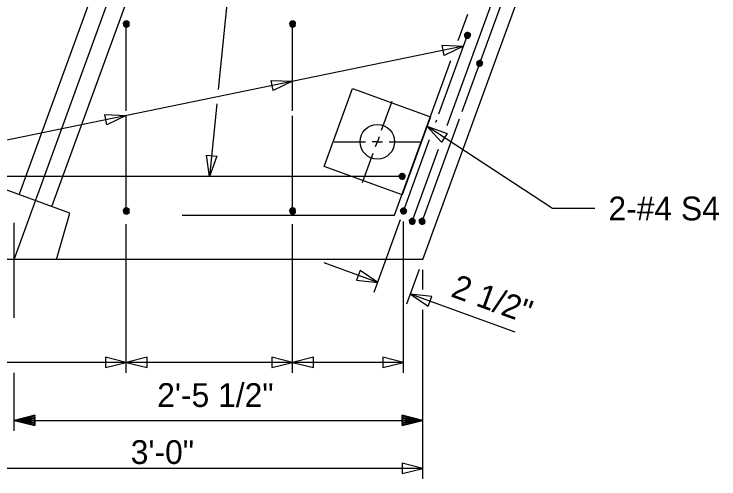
# Model space of a CAD drawing. Extents: x -408 to -23, y -15 to 117.
# Drawn here: x -86.987 to -82.749, y 40.166 to 42.962 of the extents above; entities that cross this region are included whole.
import ezdxf

# ---------------------------------------------------------------- set-up
doc = ezdxf.new("R2010")
doc.units = 0
for name, color, linetype in [('Arrowhead Terminators CELL', 7, 'Continuous'), ('Dimension Lines', 7, 'Continuous'), ('Mis Center Lines', 7, 'Continuous'), ('Rebar Lines', 7, 'Continuous'), ('Sup Concrete Girder Lines', 7, 'Continuous'), ('Sup Cored Slab Unit', 7, 'Continuous'), ('Text', 7, 'Continuous')]:
    doc.layers.add(name, color=color, linetype=linetype)

msp = doc.modelspace()

# ---------------------------------------------------------------- linework, layer by layer
at = {"layer": 'Arrowhead Terminators CELL'}
for points in [[(-84.2846, 42.7692), (-84.4008, 42.7134), (-84.4134, 42.7746)], [(-85.3123, 42.5577), (-85.4284, 42.5019), (-85.441, 42.5632)], [(-86.3123, 42.352), (-86.4284, 42.2962), (-86.441, 42.3574)], [(-84.5044, 42.287), (-84.3827, 42.2446), (-84.417, 42.1924)], [(-85.8118, 41.9859), (-85.8305, 42.1134), (-85.7683, 42.1072)], [(-84.8, 41.3484), (-84.9068, 41.4206), (-84.9282, 41.3619)], [(-84.6043, 41.2772), (-84.4975, 41.2051), (-84.4761, 41.2638)], [(-86.3123, 40.8667), (-86.4373, 40.898), (-86.4373, 40.8355)], [(-86.3123, 40.8667), (-86.1873, 40.8355), (-86.1873, 40.898)], [(-85.3123, 40.8667), (-85.4373, 40.898), (-85.4373, 40.8355)], [(-85.3123, 40.8667), (-85.1873, 40.8355), (-85.1873, 40.898)], [(-84.6456, 40.8667), (-84.7706, 40.898), (-84.7706, 40.8355)], [(-84.5284, 40.229), (-84.6534, 40.2603), (-84.6534, 40.1978)]]:
    msp.add_lwpolyline(points, close=True, dxfattribs=at)
at = {"layer": 'Dimension Lines'}
for p, q in [((-85.6503, 43.6051), (-85.7597, 42.5082)), ((-85.7684, 42.4213), (-85.8118, 41.9859)), ((-84.7776, 42.2631), (-84.7134, 42.4392)), ((-85.0617, 42.1944), (-84.8741, 42.1944)), ((-84.731, 42.1945), (-84.5435, 42.1944)), ((-84.8917, 41.9496), (-84.8275, 42.1258)), ((-86.9867, 41.134), (-86.9867, 41.7067)), ((-84.8214, 41.2897), (-84.6627, 41.7261)), ((-84.6456, 40.8037), (-84.6456, 41.715)), ((-86.3123, 40.8037), (-86.3123, 41.6974)), ((-85.3123, 40.8037), (-85.3123, 41.6974)), ((-84.8, 41.3484), (-85.1233, 41.4662)), ((-84.6257, 41.2184), (-84.5498, 41.4271)), ((-84.5284, 41.3057), (-84.5284, 41.4234)), ((-83.9743, 41.0479), (-84.6043, 41.2772)), ((-84.5284, 40.166), (-84.5284, 41.1822)), ((-86.3123, 40.8667), (-87.3123, 40.8667)), ((-85.3123, 40.8667), (-86.3123, 40.8667)), ((-84.6456, 40.8667), (-85.3123, 40.8667)), ((-86.9867, 40.4548), (-86.9867, 40.8042)), ((-86.9867, 40.5178), (-84.5284, 40.5178)), ((-84.5284, 40.229), (-87.5284, 40.229))]:
    msp.add_line(p, q, dxfattribs=at)
for points in [[(-84.2846, 42.7692), (-88.3544, 41.9318), (-88.4563, 41.9318)], [(-83.4943, 41.7927), (-83.7502, 41.7927), (-84.5044, 42.287)], [(-84.7917, 42.2239), (-84.8026, 42.1944), (-84.771, 42.1943)], [(-84.8135, 42.1648), (-84.8029, 42.1942), (-84.8343, 42.1943)], [(-86.8617, 40.5178), (-86.8617, 40.5115), (-86.9867, 40.5178), (-86.8617, 40.5053), (-86.8617, 40.499), (-86.9867, 40.5178), (-86.8617, 40.4928), (-86.8617, 40.4865), (-86.9867, 40.5178), (-86.8617, 40.549), (-86.8617, 40.5428), (-86.9867, 40.5178), (-86.8617, 40.5365), (-86.8617, 40.5303), (-86.9867, 40.5178), (-86.8617, 40.524), (-86.8617, 40.4865), (-86.8617, 40.549), (-86.9867, 40.5178), (-86.8617, 40.4865)], [(-84.6534, 40.5178), (-84.6534, 40.524), (-84.5284, 40.5178), (-84.6534, 40.5303), (-84.6534, 40.5365), (-84.5284, 40.5178), (-84.6534, 40.5428), (-84.6534, 40.549), (-84.5284, 40.5178), (-84.6534, 40.4865), (-84.6534, 40.4928), (-84.5284, 40.5178), (-84.6534, 40.499), (-84.6534, 40.5053), (-84.5284, 40.5178), (-84.6534, 40.5115), (-84.6534, 40.549), (-84.6534, 40.4865), (-84.5284, 40.5178), (-84.6534, 40.549)]]:
    msp.add_lwpolyline(points, dxfattribs=at)
at = {"layer": 'Mis Center Lines'}
msp.add_line((-86.9867, 41.4859), (-85.9162, 44.4271), dxfattribs=at)
at = {"layer": 'Rebar Lines'}
for p, q in [((-84.2927, 42.3769), (-83.9898, 43.209)), ((-84.3834, 42.292), (-84.0677, 43.1594)), ((-84.3164, 42.8036), (-84.2587, 42.962)), ((-86.3123, 42.3911), (-86.3123, 42.9025)), ((-86.3123, 42.3793), (-86.3123, 42.9025)), ((-85.3123, 42.3911), (-85.3123, 42.9025)), ((-85.3123, 42.3793), (-85.3123, 42.9025)), ((-84.4328, 42.3621), (-84.2608, 42.8347)), ((-84.6993, 41.7515), (-84.3602, 42.6831)), ((-86.3123, 41.7775), (-86.3123, 42.3502)), ((-85.3123, 41.7775), (-85.3123, 42.3502)), ((-84.5336, 41.715), (-84.3094, 42.3312)), ((-84.4509, 42.3125), (-84.4458, 42.3264)), ((-84.6456, 41.7775), (-84.4887, 42.2086)), ((-84.5934, 41.715), (-84.4349, 42.1504)), ((-84.6536, 41.9859), (-87.3411, 41.9859)), ((-85.9761, 41.7515), (-84.6993, 41.7515))]:
    msp.add_line(p, q, dxfattribs=at)
for points in [[(-86.2947, 42.9025), (-86.296, 42.9092), (-86.2998, 42.915), (-86.3055, 42.9188), (-86.3123, 42.9201), (-86.319, 42.9188), (-86.3247, 42.915), (-86.3285, 42.9093), (-86.3299, 42.9025), (-86.3285, 42.8958), (-86.3247, 42.8901), (-86.319, 42.8862), (-86.3123, 42.8849), (-86.3055, 42.8862), (-86.2998, 42.89), (-86.296, 42.8957), (-86.2947, 42.9025), (-86.3123, 42.9025), (-86.3299, 42.9025), (-86.3285, 42.9093), (-86.3123, 42.9025), (-86.3247, 42.915), (-86.319, 42.9188), (-86.3123, 42.9025), (-86.3123, 42.9201), (-86.3055, 42.9188), (-86.3123, 42.9025), (-86.2998, 42.915), (-86.296, 42.9092), (-86.3123, 42.9025), (-86.296, 42.8957), (-86.2998, 42.89), (-86.3123, 42.9025), (-86.3055, 42.8862), (-86.3123, 42.8849), (-86.3123, 42.9025), (-86.319, 42.8862), (-86.3247, 42.8901), (-86.3123, 42.9025), (-86.3285, 42.8958)], [(-85.2947, 42.9025), (-85.296, 42.9092), (-85.2998, 42.915), (-85.3055, 42.9188), (-85.3123, 42.9201), (-85.319, 42.9188), (-85.3247, 42.915), (-85.3285, 42.9093), (-85.3299, 42.9025), (-85.3285, 42.8958), (-85.3247, 42.8901), (-85.319, 42.8862), (-85.3123, 42.8849), (-85.3055, 42.8862), (-85.2998, 42.89), (-85.296, 42.8957), (-85.2947, 42.9025), (-85.3123, 42.9025), (-85.3299, 42.9025), (-85.3285, 42.9093), (-85.3123, 42.9025), (-85.3247, 42.915), (-85.319, 42.9188), (-85.3123, 42.9025), (-85.3123, 42.9201), (-85.3055, 42.9188), (-85.3123, 42.9025), (-85.2998, 42.915), (-85.296, 42.9092), (-85.3123, 42.9025), (-85.296, 42.8957), (-85.2998, 42.89), (-85.3123, 42.9025), (-85.3055, 42.8862), (-85.3123, 42.8849), (-85.3123, 42.9025), (-85.319, 42.8862), (-85.3247, 42.8901), (-85.3123, 42.9025), (-85.3285, 42.8958)], [(-84.2435, 42.8317), (-84.2436, 42.8385), (-84.2463, 42.8448), (-84.2513, 42.8496), (-84.2577, 42.852), (-84.2646, 42.8519), (-84.2709, 42.8491), (-84.2757, 42.8442), (-84.2782, 42.8378), (-84.278, 42.8309), (-84.2752, 42.8246), (-84.2703, 42.8199), (-84.2639, 42.8174), (-84.257, 42.8175), (-84.2507, 42.8203), (-84.2459, 42.8252), (-84.2435, 42.8317), (-84.2608, 42.8347), (-84.2782, 42.8378), (-84.2757, 42.8442), (-84.2608, 42.8347), (-84.2709, 42.8491), (-84.2646, 42.8519), (-84.2608, 42.8347), (-84.2577, 42.852), (-84.2513, 42.8496), (-84.2608, 42.8347), (-84.2463, 42.8448), (-84.2436, 42.8385), (-84.2608, 42.8347), (-84.2459, 42.8252), (-84.2507, 42.8203), (-84.2608, 42.8347), (-84.257, 42.8175), (-84.2639, 42.8174), (-84.2608, 42.8347), (-84.2703, 42.8199), (-84.2752, 42.8246), (-84.2608, 42.8347), (-84.278, 42.8309)], [(-84.1704, 42.6623), (-84.1705, 42.6691), (-84.1733, 42.6754), (-84.1783, 42.6802), (-84.1847, 42.6827), (-84.1915, 42.6826), (-84.1978, 42.6798), (-84.2026, 42.6748), (-84.2051, 42.6684), (-84.2049, 42.6615), (-84.2022, 42.6552), (-84.1972, 42.6504), (-84.1908, 42.6479), (-84.1839, 42.6481), (-84.1776, 42.6508), (-84.1728, 42.6558), (-84.1704, 42.6623), (-84.1877, 42.6653), (-84.2051, 42.6684), (-84.2026, 42.6748), (-84.1877, 42.6653), (-84.1978, 42.6798), (-84.1915, 42.6826), (-84.1877, 42.6653), (-84.1847, 42.6827), (-84.1783, 42.6802), (-84.1877, 42.6653), (-84.1733, 42.6754), (-84.1705, 42.6691), (-84.1877, 42.6653), (-84.1728, 42.6558), (-84.1776, 42.6508), (-84.1877, 42.6653), (-84.1839, 42.6481), (-84.1908, 42.6479), (-84.1877, 42.6653), (-84.1972, 42.6504), (-84.2022, 42.6552), (-84.1877, 42.6653), (-84.2049, 42.6615)], [(-84.6363, 41.9828), (-84.6364, 41.9897), (-84.6391, 41.996), (-84.6441, 42.0008), (-84.6506, 42.0032), (-84.6574, 42.0031), (-84.6637, 42.0003), (-84.6684, 41.9954), (-84.6709, 41.989), (-84.6708, 41.9821), (-84.668, 41.9758), (-84.6631, 41.971), (-84.6566, 41.9685), (-84.6498, 41.9687), (-84.6435, 41.9714), (-84.6387, 41.9764), (-84.6363, 41.9828), (-84.6536, 41.9859), (-84.6709, 41.989), (-84.6684, 41.9954), (-84.6536, 41.9859), (-84.6637, 42.0003), (-84.6574, 42.0031), (-84.6536, 41.9859), (-84.6506, 42.0032), (-84.6441, 42.0008), (-84.6536, 41.9859), (-84.6391, 41.996), (-84.6364, 41.9897), (-84.6536, 41.9859), (-84.6387, 41.9764), (-84.6435, 41.9714), (-84.6536, 41.9859), (-84.6498, 41.9687), (-84.6566, 41.9685), (-84.6536, 41.9859), (-84.6631, 41.971), (-84.668, 41.9758), (-84.6536, 41.9859), (-84.6708, 41.9821)], [(-86.2947, 41.7775), (-86.296, 41.7842), (-86.2998, 41.79), (-86.3055, 41.7938), (-86.3123, 41.7951), (-86.319, 41.7938), (-86.3247, 41.79), (-86.3285, 41.7843), (-86.3299, 41.7775), (-86.3285, 41.7708), (-86.3247, 41.7651), (-86.319, 41.7612), (-86.3123, 41.7599), (-86.3055, 41.7612), (-86.2998, 41.765), (-86.296, 41.7707), (-86.2947, 41.7775), (-86.3123, 41.7775), (-86.3299, 41.7775), (-86.3285, 41.7843), (-86.3123, 41.7775), (-86.3247, 41.79), (-86.319, 41.7938), (-86.3123, 41.7775), (-86.3123, 41.7951), (-86.3055, 41.7938), (-86.3123, 41.7775), (-86.2998, 41.79), (-86.296, 41.7842), (-86.3123, 41.7775), (-86.296, 41.7707), (-86.2998, 41.765), (-86.3123, 41.7775), (-86.3055, 41.7612), (-86.3123, 41.7599), (-86.3123, 41.7775), (-86.319, 41.7612), (-86.3247, 41.7651), (-86.3123, 41.7775), (-86.3285, 41.7708)], [(-85.2947, 41.7775), (-85.296, 41.7842), (-85.2998, 41.79), (-85.3055, 41.7938), (-85.3123, 41.7951), (-85.319, 41.7938), (-85.3247, 41.79), (-85.3285, 41.7843), (-85.3299, 41.7775), (-85.3285, 41.7708), (-85.3247, 41.7651), (-85.319, 41.7612), (-85.3123, 41.7599), (-85.3055, 41.7612), (-85.2998, 41.765), (-85.296, 41.7707), (-85.2947, 41.7775), (-85.3123, 41.7775), (-85.3299, 41.7775), (-85.3285, 41.7843), (-85.3123, 41.7775), (-85.3247, 41.79), (-85.319, 41.7938), (-85.3123, 41.7775), (-85.3123, 41.7951), (-85.3055, 41.7938), (-85.3123, 41.7775), (-85.2998, 41.79), (-85.296, 41.7842), (-85.3123, 41.7775), (-85.296, 41.7707), (-85.2998, 41.765), (-85.3123, 41.7775), (-85.3055, 41.7612), (-85.3123, 41.7599), (-85.3123, 41.7775), (-85.319, 41.7612), (-85.3247, 41.7651), (-85.3123, 41.7775), (-85.3285, 41.7708)], [(-84.6283, 41.7744), (-84.6284, 41.7813), (-84.6311, 41.7876), (-84.6361, 41.7924), (-84.6425, 41.7949), (-84.6493, 41.7948), (-84.6557, 41.7919), (-84.6604, 41.787), (-84.6629, 41.7806), (-84.6627, 41.7737), (-84.66, 41.7674), (-84.6551, 41.7626), (-84.6487, 41.7601), (-84.6417, 41.7603), (-84.6355, 41.763), (-84.6307, 41.768), (-84.6283, 41.7744), (-84.6456, 41.7775), (-84.6629, 41.7806), (-84.6604, 41.787), (-84.6456, 41.7775), (-84.6557, 41.7919), (-84.6493, 41.7948), (-84.6456, 41.7775), (-84.6425, 41.7949), (-84.6361, 41.7924), (-84.6456, 41.7775), (-84.6311, 41.7876), (-84.6284, 41.7813), (-84.6456, 41.7775), (-84.6307, 41.768), (-84.6355, 41.763), (-84.6456, 41.7775), (-84.6417, 41.7603), (-84.6487, 41.7601), (-84.6456, 41.7775), (-84.6551, 41.7626), (-84.66, 41.7674), (-84.6456, 41.7775), (-84.6627, 41.7737)], [(-84.576, 41.712), (-84.5762, 41.7188), (-84.5789, 41.7251), (-84.5839, 41.7299), (-84.5903, 41.7324), (-84.5972, 41.7323), (-84.6035, 41.7294), (-84.6082, 41.7245), (-84.6107, 41.7181), (-84.6105, 41.7113), (-84.6078, 41.705), (-84.6029, 41.7002), (-84.5964, 41.6977), (-84.5896, 41.6978), (-84.5833, 41.7006), (-84.5785, 41.7055), (-84.576, 41.712), (-84.5934, 41.715), (-84.6107, 41.7181), (-84.6082, 41.7245), (-84.5934, 41.715), (-84.6035, 41.7294), (-84.5972, 41.7323), (-84.5934, 41.715), (-84.5903, 41.7324), (-84.5839, 41.7299), (-84.5934, 41.715), (-84.5789, 41.7251), (-84.5762, 41.7188), (-84.5934, 41.715), (-84.5785, 41.7055), (-84.5833, 41.7006), (-84.5934, 41.715), (-84.5896, 41.6978), (-84.5964, 41.6977), (-84.5934, 41.715), (-84.6029, 41.7002), (-84.6078, 41.705), (-84.5934, 41.715), (-84.6105, 41.7113)], [(-84.5163, 41.7119), (-84.5164, 41.7188), (-84.5191, 41.7251), (-84.5241, 41.7299), (-84.5305, 41.7324), (-84.5374, 41.7323), (-84.5437, 41.7294), (-84.5484, 41.7245), (-84.5509, 41.7181), (-84.5508, 41.7112), (-84.548, 41.7049), (-84.5431, 41.7001), (-84.5366, 41.6976), (-84.5298, 41.6978), (-84.5235, 41.7005), (-84.5187, 41.7055), (-84.5163, 41.7119), (-84.5336, 41.715), (-84.5509, 41.7181), (-84.5484, 41.7245), (-84.5336, 41.715), (-84.5437, 41.7294), (-84.5374, 41.7323), (-84.5336, 41.715), (-84.5305, 41.7324), (-84.5241, 41.7299), (-84.5336, 41.715), (-84.5191, 41.7251), (-84.5164, 41.7188), (-84.5336, 41.715), (-84.5187, 41.7055), (-84.5235, 41.7005), (-84.5336, 41.715), (-84.5298, 41.6978), (-84.5366, 41.6976), (-84.5336, 41.715), (-84.5431, 41.7001), (-84.548, 41.7049), (-84.5336, 41.715), (-84.5508, 41.7112)]]:
    msp.add_lwpolyline(points, dxfattribs=at)
at = {"layer": 'Sup Concrete Girder Lines'}
for p, q in [((-86.9557, 41.8757), (-86.0056, 44.4859)), ((-86.7599, 41.8044), (-85.7839, 44.4859)), ((-84.5284, 41.4859), (-83.4578, 44.4271)), ((-84.5284, 41.4859), (-88.2718, 41.4859))]:
    msp.add_line(p, q, dxfattribs=at)
msp.add_lwpolyline([(-86.7318, 41.4859), (-86.6523, 41.7652), (-87.0634, 41.9149), (-87.2417, 41.4859)], dxfattribs=at)
msp.add_circle((-84.8029, 42.1942), 0.1042, dxfattribs=at)
at = {"layer": 'Sup Cored Slab Unit'}
msp.add_lwpolyline([(-84.9523, 42.5147), (-84.4824, 42.3436), (-84.6535, 41.8738), (-85.1233, 42.0448)], close=True, dxfattribs=at)

# ---------------------------------------------------------------- texts
at = {"layer": 'Text'}
for s, p in [('2-#4 S4', (-83.4134, 41.7212)), ('2\'-5 1/2"', (-86.1264, 40.5988)), ('3\'-0"', (-86.2857, 40.2558))]:
    msp.add_text(s, height=0.14302, dxfattribs=at).set_placement(p)
msp.add_text('2 1/2"', height=0.14302, rotation=339.9998, dxfattribs=at).set_placement((-84.3676, 41.2653))

doc.saveas('drawing.dxf')
